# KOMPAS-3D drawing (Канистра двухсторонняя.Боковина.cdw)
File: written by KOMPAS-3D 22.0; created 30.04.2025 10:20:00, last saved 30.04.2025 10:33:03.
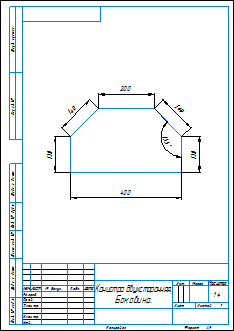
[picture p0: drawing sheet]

Sheet 1: A4, portrait

Document properties: Автор: Admin; Наименование: Канистра двухсторонняя. Боковина; Полное имя файла: D:\28.11.2016\3D модели\Абилимпикс\2025\Канистра двухсторонняя\Канистра двухсторонняя.Боковина.cdw

Title block, sheet 1: Наименование: Канистра двухсторонняя. / Боковина.; scale: 1:4; Количество листов документа: 1; Форматы листов документа: A4

Dimensions and other numbers on the sheet: 400; 130; 140; 200; 135; 1:4; 1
